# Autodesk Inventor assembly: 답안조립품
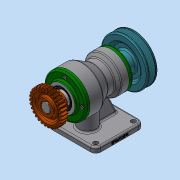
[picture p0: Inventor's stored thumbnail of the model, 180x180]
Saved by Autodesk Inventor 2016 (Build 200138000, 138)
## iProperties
Created: 2019-01
Part Number: 답안조립품
Document SubType Name: Assembly
Designer: Administrator
Author: Administrator
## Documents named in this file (15)
- C:\Users\Administrator\Desktop\490107V1037\답안조립품.iam
- C:\Users\Administrator\Desktop\490107V1037\본체.ipt
- C:\Users\Administrator\Desktop\490107V1037\베어링 6205.ipt
- C:\Users\Administrator\Desktop\490107V1037\베어링 6203.ipt
- C:\Users\Administrator\Desktop\490107V1037\축.ipt
- C:\Users\Administrator\Desktop\490107V1037\앞커버.ipt
- C:\Users\Administrator\Desktop\490107V1037\오일 실 25 38 8.ipt
- C:\Users\Administrator\Desktop\490107V1037\키 6 x 6 x 18.ipt
- C:\Users\Administrator\Desktop\490107V1037\스퍼기어.ipt
- C:\Users\Administrator\Desktop\490107V1037\뒤커버.ipt
- C:\Users\Administrator\Desktop\490107V1037\오일 실 17 30 8.ipt
- C:\Users\Administrator\Desktop\490107V1037\키 5 x 5 x 20.ipt
- C:\Users\Administrator\Desktop\490107V1037\V-벨트풀리.ipt
- C:\Users\Administrator\Desktop\490107V1037\멈춤나사 M3.ipt
- C:\Users\Administrator\Desktop\490107V1037\볼트 M4.ipt
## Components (1 placed, 1 different names)
1. V-벨트풀리:1
